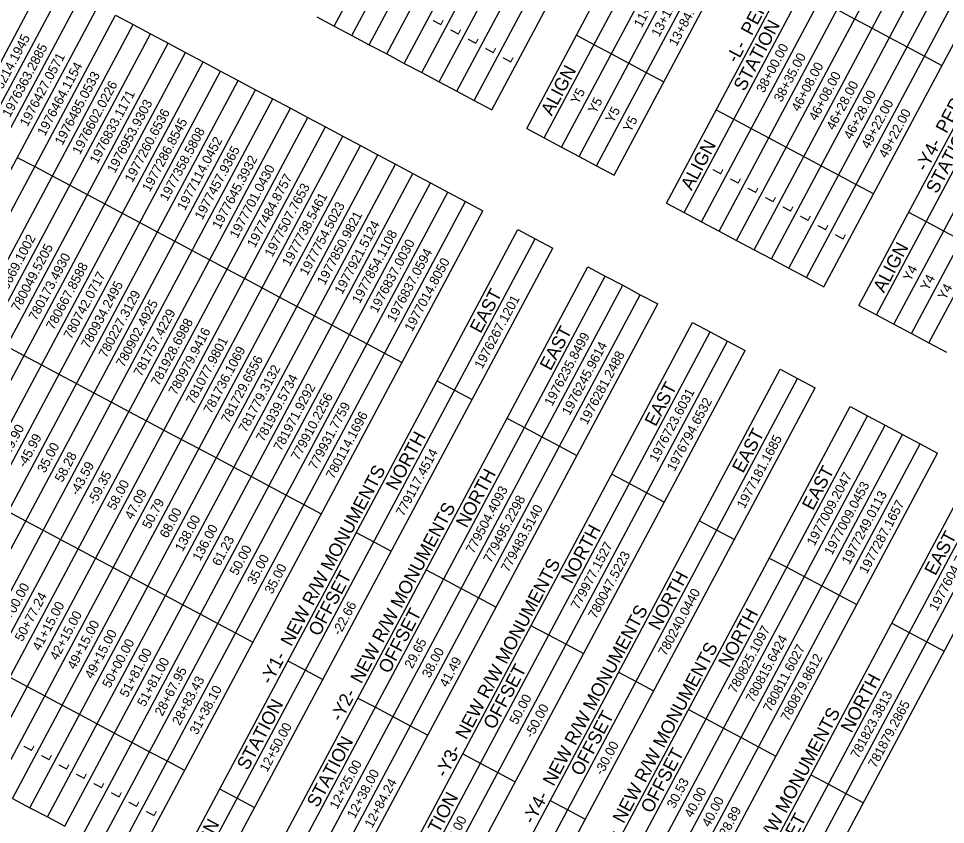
# Model space of a CAD drawing. Extents: x 1979034 to 1987549, y 771535 to 781988.
# Drawn here: x 1981883 to 1984093, y 775446 to 777368 of the extents above; entities that cross this region are included whole.
import ezdxf

# ---------------------------------------------------------------- set-up
doc = ezdxf.new("R2010")
doc.units = 0
for name, color, linetype in [('CTL Sheet Notes CELL', 7, 'Continuous'), ('CTL Sheet Table Cell', 7, 'Continuous'), ('CTL Sheet Text', 7, 'Continuous')]:
    doc.layers.add(name, color=color, linetype=linetype)

msp = doc.modelspace()

# ---------------------------------------------------------------- linework, layer by layer
at = {"layer": 'CTL Sheet Table Cell'}
for p, q in [((1982636.1, 777349.6), (1983465.7, 778906.4)), ((1982677.8, 777327.4), (1983507.4, 778884.1)), ((1982719.5, 777305.2), (1983549.1, 778861.9)), ((1982761.2, 777283), (1983590.8, 778839.7)), ((1982802.9, 777260.7), (1983632.5, 778817.5)), ((1982844.6, 777238.5), (1983674.2, 778795.3)), ((1982886.3, 777216.3), (1983715.9, 778773)), ((1982928, 777194.1), (1983757.6, 778750.8)), ((1982969.7, 777171.8), (1983799.3, 778728.6)), ((1983011.4, 777149.6), (1983841, 778706.4)), ((1983094.8, 777105.2), (1983924.4, 778661.9)), ((1983136.5, 777083), (1983966.1, 778639.7)), ((1983178.2, 777060.7), (1984007.8, 778617.5)), ((1983219.9, 777038.5), (1984049.5, 778595.3)), ((1983261.6, 777016.3), (1984091.2, 778573.1)), ((1983303.3, 776994.1), (1984132.9, 778550.8)), ((1983428.4, 776927.4), (1984258, 778484.2)), ((1983470.1, 776905.2), (1984299.7, 778462)), ((1983511.8, 776883), (1984341.4, 778439.7)), ((1983553.5, 776860.8), (1984383.1, 778417.5)), ((1983595.2, 776838.5), (1984424.8, 778395.3)), ((1983636.9, 776816.3), (1984466.5, 778373.1)), ((1983678.6, 776794.1), (1984508.2, 778350.8)), ((1983720.3, 776771.9), (1984549.9, 778328.6)), ((1983762, 776749.6), (1984591.6, 778306.4)), ((1983803.7, 776727.4), (1984633.3, 778284.2)), ((1983887.1, 776683), (1984716.7, 778239.7)), ((1983928.8, 776660.8), (1984758.4, 778217.5)), ((1983970.5, 776638.5), (1984800.1, 778195.3)), ((1984012.2, 776616.3), (1984841.7, 778173.1)), ((1984053.9, 776594.1), (1984883.4, 778150.9)), ((1981118.2, 775907.8), (1981947.8, 777464.6)), ((1981159.9, 775885.6), (1981989.5, 777442.3)), ((1981201.6, 775863.4), (1982031.2, 777420.1)), ((1981243.3, 775841.1), (1982072.9, 777397.9)), ((1983834.9, 777388.9), (1983876.6, 777366.7)), ((1981285, 775818.9), (1982114.6, 777375.7)), ((1982114.6, 777375.7), (1982156.3, 777353.5)), ((1982594.4, 777371.8), (1982636.1, 777349.6)), ((1983876.6, 777366.7), (1983918.3, 777344.5)), ((1981326.7, 775796.7), (1982156.3, 777353.5)), ((1982156.3, 777353.5), (1982198, 777331.2)), ((1982636.1, 777349.6), (1982677.8, 777327.4)), ((1983918.3, 777344.5), (1983960, 777322.3)), ((1981368.4, 775774.5), (1982198, 777331.2)), ((1982198, 777331.2), (1982239.7, 777309)), ((1982677.8, 777327.4), (1982719.5, 777305.2)), ((1983213.3, 777327.6), (1983255, 777305.4)), ((1983960, 777322.3), (1984001.7, 777300.1)), ((1981410.1, 775752.3), (1982239.7, 777309)), ((1982239.7, 777309), (1982281.4, 777286.8)), ((1982719.5, 777305.2), (1982761.2, 777283)), ((1983255, 777305.4), (1983296.7, 777283.1)), ((1984001.7, 777300.1), (1984043.4, 777277.8)), ((1981451.8, 775730), (1982281.4, 777286.8)), ((1982281.4, 777286.8), (1982323.1, 777264.6)), ((1982761.2, 777283), (1982802.9, 777260.7)), ((1983296.7, 777283.1), (1983338.4, 777260.9)), ((1984043.4, 777277.8), (1984085.1, 777255.6)), ((1981493.5, 775707.8), (1982323.1, 777264.6)), ((1982323.1, 777264.6), (1982364.8, 777242.3)), ((1982802.9, 777260.7), (1982844.6, 777238.5)), ((1983338.4, 777260.9), (1983380.1, 777238.7)), ((1981535.2, 775685.6), (1982364.8, 777242.3)), ((1982364.8, 777242.3), (1982406.5, 777220.1)), ((1982844.6, 777238.5), (1982886.3, 777216.3)), ((1983380.1, 777238.7), (1983421.8, 777216.5)), ((1981576.9, 775663.4), (1982406.5, 777220.1)), ((1982406.5, 777220.1), (1982448.2, 777197.9)), ((1982886.3, 777216.3), (1982928, 777194.1)), ((1981618.6, 775641.1), (1982448.2, 777197.9)), ((1982448.2, 777197.9), (1982489.9, 777175.7)), ((1982928, 777194.1), (1982969.7, 777171.8)), ((1981660.3, 775618.9), (1982489.9, 777175.7)), ((1982489.9, 777175.7), (1982531.6, 777153.5)), ((1982969.7, 777171.8), (1983011.4, 777149.6)), ((1981702, 775596.7), (1982531.6, 777153.5)), ((1982531.6, 777153.5), (1982573.3, 777131.2)), ((1983546.9, 777149.8), (1983588.6, 777127.6)), ((1981743.7, 775574.5), (1982573.3, 777131.2)), ((1982573.3, 777131.2), (1982615, 777109)), ((1983588.6, 777127.6), (1983630.3, 777105.4)), ((1981785.4, 775552.3), (1982615, 777109)), ((1982615, 777109), (1982656.7, 777086.8)), ((1983094.8, 777105.2), (1983136.5, 777083)), ((1983630.3, 777105.4), (1983672, 777083.1)), ((1981827.1, 775530), (1982656.7, 777086.8)), ((1982656.7, 777086.8), (1982698.4, 777064.6)), ((1983136.5, 777083), (1983178.2, 777060.7)), ((1983672, 777083.1), (1983713.7, 777060.9)), ((1981868.8, 775507.8), (1982698.4, 777064.6)), ((1982698.4, 777064.6), (1982740.1, 777042.4)), ((1983178.2, 777060.7), (1983219.9, 777038.5)), ((1983713.7, 777060.9), (1983755.4, 777038.7)), ((1981880.3, 777036.5), (1981922, 777014.3)), ((1981910.5, 775485.6), (1982740.1, 777042.4)), ((1982740.1, 777042.4), (1982781.8, 777020.1)), ((1983219.9, 777038.5), (1983261.6, 777016.3)), ((1983755.4, 777038.7), (1983797.1, 777016.5)), ((1981922, 777014.3), (1981963.7, 776992.1)), ((1981952.2, 775463.4), (1982781.8, 777020.1)), ((1982781.8, 777020.1), (1982823.5, 776997.9)), ((1983261.6, 777016.3), (1983303.3, 776994.1)), ((1983797.1, 777016.5), (1983838.8, 776994.3)), ((1981963.7, 776992.1), (1982005.4, 776969.8)), ((1981993.9, 775441.2), (1982823.5, 776997.9)), ((1982823.5, 776997.9), (1982865.2, 776975.7)), ((1983838.8, 776994.3), (1983880.5, 776972)), ((1982005.4, 776969.8), (1982047.1, 776947.6)), ((1982035.6, 775418.9), (1982865.2, 776975.7)), ((1982865.2, 776975.7), (1982906.9, 776953.5)), ((1983880.5, 776972), (1983922.2, 776949.8)), ((1982047.1, 776947.6), (1982088.8, 776925.4)), ((1982077.3, 775396.7), (1982906.9, 776953.5)), ((1982906.9, 776953.5), (1982948.6, 776931.3)), ((1982088.8, 776925.4), (1982130.5, 776903.2)), ((1982119, 775374.5), (1982948.6, 776931.3)), ((1982948.6, 776931.3), (1982990.3, 776909)), ((1983428.4, 776927.4), (1983470.1, 776905.2)), ((1982130.5, 776903.2), (1982172.2, 776881)), ((1982160.7, 775352.3), (1982990.3, 776909)), ((1983470.1, 776905.2), (1983511.8, 776883)), ((1984005.6, 776905.4), (1984047.3, 776883.2)), ((1982172.2, 776881), (1982213.9, 776858.7)), ((1983511.8, 776883), (1983553.5, 776860.8)), ((1984047.3, 776883.2), (1984089, 776860.9)), ((1982213.9, 776858.7), (1982255.6, 776836.5)), ((1982244.1, 775307.8), (1983073.7, 776864.6)), ((1983073.7, 776864.6), (1983115.4, 776842.4)), ((1983553.5, 776860.8), (1983595.2, 776838.5)), ((1984089, 776860.9), (1984130.7, 776838.7)), ((1982255.6, 776836.5), (1982297.3, 776814.3)), ((1982285.8, 775285.6), (1983115.4, 776842.4)), ((1983115.4, 776842.4), (1983157.1, 776820.1)), ((1983595.2, 776838.5), (1983636.9, 776816.3)), ((1982297.3, 776814.3), (1982339, 776792.1)), ((1982327.5, 775263.4), (1983157.1, 776820.1)), ((1983636.9, 776816.3), (1983678.6, 776794.1)), ((1982339, 776792.1), (1982380.7, 776769.9)), ((1983678.6, 776794.1), (1983720.3, 776771.9)), ((1982380.7, 776769.9), (1982422.4, 776747.6)), ((1982410.9, 775218.9), (1983240.5, 776775.7)), ((1983240.5, 776775.7), (1983282.2, 776753.5)), ((1983720.3, 776771.9), (1983762, 776749.6)), ((1982422.4, 776747.6), (1982464.1, 776725.4)), ((1982452.6, 775196.7), (1983282.2, 776753.5)), ((1983282.2, 776753.5), (1983323.9, 776731.3)), ((1983762, 776749.6), (1983803.7, 776727.4)), ((1982464.1, 776725.4), (1982505.8, 776703.2)), ((1982494.3, 775174.5), (1983323.9, 776731.3)), ((1983323.9, 776731.3), (1983365.5, 776709)), ((1982505.8, 776703.2), (1982547.5, 776681)), ((1982536, 775152.3), (1983365.5, 776709)), ((1983365.5, 776709), (1983407.2, 776686.8)), ((1982547.5, 776681), (1982589.2, 776658.7)), ((1982577.7, 775130.1), (1983407.2, 776686.8)), ((1983887.1, 776683), (1983928.8, 776660.8)), ((1982589.2, 776658.7), (1982630.9, 776636.5)), ((1983928.8, 776660.8), (1983970.5, 776638.5)), ((1982630.9, 776636.5), (1982672.6, 776614.3)), ((1982661.1, 775085.6), (1983490.6, 776642.4)), ((1983490.6, 776642.4), (1983532.3, 776620.2)), ((1983970.5, 776638.5), (1984012.2, 776616.3)), ((1982672.6, 776614.3), (1982714.3, 776592.1)), ((1982702.8, 775063.4), (1983532.3, 776620.2)), ((1983532.3, 776620.2), (1983574, 776597.9)), ((1984012.2, 776616.3), (1984053.9, 776594.1)), ((1981854.5, 776586.2), (1981896.2, 776564)), ((1982714.3, 776592.1), (1982756, 776569.9)), ((1982744.5, 775041.2), (1983574, 776597.9)), ((1983574, 776597.9), (1983615.7, 776575.7)), ((1984053.9, 776594.1), (1984095.6, 776571.9)), ((1981896.2, 776564), (1981937.9, 776541.8)), ((1982756, 776569.9), (1982797.7, 776547.6)), ((1982786.2, 775019), (1983615.7, 776575.7)), ((1981937.9, 776541.8), (1981979.6, 776519.6)), ((1981979.6, 776519.6), (1982021.3, 776497.3)), ((1982869.6, 774974.5), (1983699.1, 776531.3)), ((1983699.1, 776531.3), (1983740.8, 776509.1)), ((1982021.3, 776497.3), (1982063, 776475.1)), ((1982881.1, 776503.2), (1982922.8, 776481)), ((1982911.3, 774952.3), (1983740.8, 776509.1)), ((1983740.8, 776509.1), (1983782.5, 776486.8)), ((1982063, 776475.1), (1982104.7, 776452.9)), ((1982922.8, 776481), (1982964.5, 776458.8)), ((1982953, 774930.1), (1983782.5, 776486.8)), ((1982104.7, 776452.9), (1982146.4, 776430.7)), ((1982146.4, 776430.7), (1982188.1, 776408.5)), ((1983036.3, 774885.6), (1983865.9, 776442.4)), ((1983865.9, 776442.4), (1983907.6, 776420.2)), ((1982188.1, 776408.5), (1982229.8, 776386.2)), ((1983047.9, 776414.3), (1983089.6, 776392.1)), ((1983078, 774863.4), (1983907.6, 776420.2)), ((1983907.6, 776420.2), (1983949.3, 776397.9)), ((1982229.8, 776386.2), (1982271.5, 776364)), ((1983089.6, 776392.1), (1983131.3, 776369.9)), ((1983119.7, 774841.2), (1983949.3, 776397.9)), ((1983949.3, 776397.9), (1983991, 776375.7)), ((1982271.5, 776364), (1982313.2, 776341.8)), ((1983131.3, 776369.9), (1983173, 776347.7)), ((1983161.4, 774819), (1983991, 776375.7)), ((1983991, 776375.7), (1984032.7, 776353.5)), ((1982313.2, 776341.8), (1982354.9, 776319.6)), ((1983173, 776347.7), (1983214.7, 776325.4)), ((1983203.1, 774796.7), (1984032.7, 776353.5)), ((1984032.7, 776353.5), (1984074.4, 776331.3)), ((1982354.9, 776319.6), (1982396.6, 776297.4)), ((1983244.8, 774774.5), (1984074.4, 776331.3)), ((1982396.6, 776297.4), (1982438.3, 776275.1)), ((1982438.3, 776275.1), (1982480, 776252.9)), ((1983298.1, 776281), (1983339.8, 776258.8)), ((1983328.2, 774730.1), (1984157.8, 776286.8)), ((1982480, 776252.9), (1982521.7, 776230.7)), ((1983339.8, 776258.8), (1983381.5, 776236.5)), ((1983369.9, 774707.9), (1984199.5, 776264.6)), ((1982521.7, 776230.7), (1982563.4, 776208.5)), ((1983381.5, 776236.5), (1983423.2, 776214.3)), ((1983411.6, 774685.6), (1984241.2, 776242.4)), ((1982563.4, 776208.5), (1982605.1, 776186.3)), ((1983453.3, 774663.4), (1984282.9, 776220.2)), ((1981858.4, 776191.6), (1981900.1, 776169.3)), ((1981900.1, 776169.3), (1981941.8, 776147.1)), ((1983506.6, 776169.9), (1983548.3, 776147.7)), ((1981941.8, 776147.1), (1981983.5, 776124.9)), ((1982688.5, 776141.8), (1982730.2, 776119.6)), ((1983548.3, 776147.7), (1983590, 776125.4)), ((1981983.5, 776124.9), (1982025.2, 776102.7)), ((1982730.2, 776119.6), (1982771.9, 776097.4)), ((1982025.2, 776102.7), (1982066.9, 776080.4)), ((1982066.9, 776080.4), (1982108.6, 776058.2)), ((1983673.4, 776081), (1983715.1, 776058.8)), ((1982108.6, 776058.2), (1982150.2, 776036)), ((1982855.3, 776052.9), (1982897, 776030.7)), ((1983715.1, 776058.8), (1983756.7, 776036.6)), ((1982150.2, 776036), (1982191.9, 776013.8)), ((1982897, 776030.7), (1982938.7, 776008.5)), ((1983756.7, 776036.6), (1983798.4, 776014.3)), ((1982191.9, 776013.8), (1982233.6, 775991.6)), ((1982938.7, 776008.5), (1982980.4, 775986.3)), ((1983798.4, 776014.3), (1983840.1, 775992.1)), ((1982233.6, 775991.6), (1982275.3, 775969.3)), ((1982980.4, 775986.3), (1983022.1, 775964)), ((1983840.1, 775992.1), (1983881.8, 775969.9)), ((1982275.3, 775969.3), (1982317, 775947.1)), ((1982317, 775947.1), (1982358.7, 775924.9)), ((1982358.7, 775924.9), (1982400.4, 775902.7)), ((1983105.5, 775919.6), (1983147.2, 775897.4)), ((1983965.2, 775925.5), (1984006.9, 775903.2)), ((1982400.4, 775902.7), (1982442.1, 775880.5)), ((1983147.2, 775897.4), (1983188.9, 775875.2)), ((1984006.9, 775903.2), (1984048.6, 775881)), ((1983188.9, 775875.2), (1983230.6, 775852.9)), ((1984048.6, 775881), (1984090.3, 775858.8)), ((1982525.5, 775836), (1982567.2, 775813.8)), ((1982567.2, 775813.8), (1982608.9, 775791.6)), ((1983314, 775808.5), (1983355.7, 775786.3)), ((1981862.2, 775796.9), (1981903.9, 775774.7)), ((1983355.7, 775786.3), (1983397.4, 775764.1)), ((1981903.9, 775774.7), (1981945.6, 775752.4)), ((1981945.6, 775752.4), (1981987.3, 775730.2)), ((1982692.3, 775747.1), (1982734, 775724.9)), ((1981987.3, 775730.2), (1982029, 775708)), ((1982734, 775724.9), (1982775.7, 775702.7)), ((1983480.8, 775719.6), (1983522.5, 775697.4)), ((1982029, 775708), (1982070.7, 775685.8)), ((1982775.7, 775702.7), (1982817.4, 775680.5)), ((1983522.5, 775697.4), (1983564.2, 775675.2)), ((1982070.7, 775685.8), (1982112.4, 775663.6)), ((1982817.4, 775680.5), (1982859.1, 775658.2)), ((1983564.2, 775675.2), (1983605.9, 775652.9)), ((1982112.4, 775663.6), (1982154.1, 775641.3)), ((1983605.9, 775652.9), (1983647.6, 775630.7)), ((1982154.1, 775641.3), (1982195.8, 775619.1)), ((1983647.6, 775630.7), (1983689.3, 775608.5)), ((1982195.8, 775619.1), (1982237.5, 775596.9)), ((1982942.5, 775613.8), (1982984.2, 775591.6)), ((1982237.5, 775596.9), (1982279.2, 775574.7)), ((1982984.2, 775591.6), (1983025.9, 775569.4)), ((1983025.9, 775569.4), (1983067.6, 775547.1)), ((1983772.7, 775564.1), (1983814.4, 775541.8)), ((1983814.4, 775541.8), (1983856.1, 775519.6)), ((1982362.6, 775530.2), (1982404.3, 775508)), ((1983856.1, 775519.6), (1983897.8, 775497.4)), ((1981868.8, 775507.8), (1981910.5, 775485.6)), ((1982404.3, 775508), (1982446, 775485.8)), ((1983151, 775502.7), (1983192.7, 775480.5)), ((1981910.5, 775485.6), (1981952.2, 775463.4)), ((1983192.7, 775480.5), (1983234.4, 775458.3)), ((1981952.2, 775463.4), (1981993.9, 775441.2))]:
    msp.add_line(p, q, dxfattribs=at)

# ---------------------------------------------------------------- texts
at = {"layer": 'CTL Sheet Notes CELL'}
for s, p in [('-L-  PERMANENT DRAINAGE EASEMENTS', (1983596.2, 777259)), ('-Y4-  PERMANENT DRAINAGE EASEMENTS', (1984047.5, 777000.8)), ('STATION', (1983614.1, 777192.3)), ('ALIGN', (1983154.5, 777133.5)), ('STATION', (1984072.8, 776947.8)), ('ALIGN', (1983488.1, 776955.7)), ('ALIGN', (1983946.8, 776711.3)), ('EAST', (1982985.2, 776614.8)), ('EAST', (1983152, 776525.9)), ('EAST', (1983402.2, 776392.6)), ('NORTH', (1982785.2, 776239.6)), ('EAST', (1983610.7, 776281.5)), ('-Y1-  NEW R/W MONUMENTS', (1982485.3, 775777.3)), ('NORTH', (1982952, 776150.7)), ('EAST', (1983777.4, 776192.6)), ('-Y2-  NEW R/W MONUMENTS', (1982652.1, 775688.5)), ('NORTH', (1983202.2, 776017.4)), ('EAST', (1984069.3, 776037.1)), ('-Y3-  NEW R/W MONUMENTS', (1982902.3, 775555.1)), ('OFFSET', (1982600.1, 775892.3)), ('NORTH', (1983410.7, 775906.3)), ('OFFSET', (1982766.9, 775803.4)), ('-Y4-  NEW R/W MONUMENTS', (1983110.8, 775444)), ('NORTH', (1983577.5, 775817.4)), ('-Y5-  NEW R/W MONUMENTS', (1983277.6, 775355.1)), ('OFFSET', (1983017.1, 775670)), ('NORTH', (1983869.4, 775661.9)), ('STATION', (1982429.8, 775572.7)), ('OFFSET', (1983225.6, 775558.9)), ('-Y6-  NEW R/W MONUMENTS', (1983569.5, 775199.6)), ('STATION', (1982596.6, 775483.8)), ('OFFSET', (1983392.4, 775470.1)), ('STATION', (1982846.8, 775350.5)), ('ALIGN', (1982303.8, 775336.2)), ('OFFSET', (1983684.3, 775314.5))]:
    msp.add_text(s, height=31.5, rotation=61.9471, dxfattribs=at).set_placement(p)
at = {"layer": 'CTL Sheet Text'}
for s, p in [('11+88.00', (1983368.7, 777344.1)), ('13+11.00', (1983410.4, 777321.9)), ('13+84.00', (1983452.1, 777299.7)), ('L', (1982889.4, 777349)), ('L', (1982931.1, 777326.7)), ('1976214.1945', (1981821, 777152.5)), ('L', (1982972.8, 777304.5)), ('1976363.2885', (1981862.7, 777130.3)), ('L', (1983014.5, 777282.3)), ('38+00.00', (1983660.6, 777188.6)), ('1976427.0571', (1981904.4, 777108.1)), ('L', (1983056.2, 777260.1)), ('38+35.00', (1983702.3, 777166.3)), ('1976464.1154', (1981946.1, 777085.9)), ('46+08.00', (1983744, 777144.1)), ('1976485.0533', (1981987.8, 777063.7)), ('46+08.00', (1983785.7, 777121.9)), ('1976602.0226', (1982029.5, 777041.4)), ('Y5', (1983217.8, 777161.3)), ('46+28.00', (1983827.4, 777099.7)), ('1976833.1171', (1982071.2, 777019.2)), ('Y5', (1983259.5, 777139.1)), ('46+28.00', (1983869.1, 777077.5)), ('1976953.9303', (1982112.9, 776997)), ('Y5', (1983301.2, 777116.9)), ('49+22.00', (1983910.8, 777055.2)), ('1977260.6536', (1982154.6, 776974.8)), ('Y5', (1983342.9, 777094.7)), ('49+22.00', (1983952.5, 777033)), ('1977286.8545', (1982196.3, 776952.6)), ('1977358.5808', (1982238, 776930.3)), ('1977114.0452', (1982279.7, 776908.1)), ('1977457.9365', (1982321.4, 776885.9)), ('1977645.3932', (1982363.1, 776863.7)), ('1977701.0430', (1982404.8, 776841.4)), ('L', (1983556.6, 776993.4)), ('1977484.8757', (1982446.5, 776819.2)), ('L', (1983598.3, 776971.2)), ('1977507.7653', (1982488.2, 776797)), ('L', (1983640, 776949)), ('1977738.5461', (1982529.9, 776774.8)), ('L', (1983681.7, 776926.8)), ('1977754.5023', (1982571.6, 776752.6)), ('L', (1983723.4, 776904.5)), ('1977850.9821', (1982613.3, 776730.3)), ('L', (1983765.1, 776882.3)), ('1977921.5124', (1982655, 776708.1)), ('L', (1983806.8, 776860.1)), ('779669.1002', (1981842.2, 776689.9)), ('1977854.1108', (1982696.7, 776685.9)), ('L', (1983848.5, 776837.9)), ('780049.5205', (1981883.9, 776667.7)), ('1976837.0030', (1982738.4, 776663.7)), ('780173.4930', (1981925.6, 776645.5)), ('1976837.0594', (1982780.1, 776641.5)), ('780667.8588', (1981967.3, 776623.2)), ('1977014.8050', (1982821.8, 776619.2)), ('780742.0717', (1982009, 776601)), ('Y4', (1984010.1, 776739.1)), ('780934.2495', (1982050.7, 776578.8)), ('Y4', (1984051.8, 776716.9)), ('780227.3129', (1982092.4, 776556.6)), ('Y4', (1984093.4, 776694.7)), ('780902.4925', (1982134.1, 776534.4)), ('1976267.1201', (1982988.6, 776530.4)), ('781757.4229', (1982175.8, 776512.1)), ('781928.6988', (1982217.5, 776489.9)), ('780979.9416', (1982259.2, 776467.7)), ('781077.9801', (1982300.9, 776445.5)), ('1976235.8499', (1983155.4, 776441.5)), ('781736.1069', (1982342.6, 776423.2)), ('1976245.9614', (1983197.1, 776419.2)), ('781729.6556', (1982384.3, 776401)), ('1976281.2488', (1983238.8, 776397)), ('781779.3132', (1982426, 776378.8)), ('781939.5734', (1982467.7, 776356.6)), ('781971.9292', (1982509.4, 776334.4)), ('779910.2256', (1982551.1, 776312.1)), ('1976723.6031', (1983405.6, 776308.1)), ('779931.7759', (1982592.8, 776289.9)), ('1976794.6532', (1983447.3, 776285.9)), ('780114.1696', (1982634.5, 776267.7)), ('-49.90', (1981857.5, 776316.7)), ('-45.99', (1981899.2, 776294.5)), ('1977181.1685', (1983614.1, 776197)), ('35.00', (1981946.1, 776282.1)), ('779117.4514', (1982801.3, 776178.8)), ('58.28', (1981987.8, 776259.9)), ('-43.59', (1982024.3, 776227.8)), ('-59.35', (1982066, 776205.6)), ('1977009.2047', (1983780.9, 776108.2)), ('58.00', (1982112.9, 776193.2)), ('779504.4093', (1982968.1, 776089.9)), ('1977009.0453', (1983822.6, 776085.9)), ('47.09', (1982154.6, 776171)), ('779495.2298', (1983009.8, 776067.7)), ('1977249.0113', (1983864.3, 776063.7)), ('50.79', (1982196.3, 776148.8)), ('779483.5140', (1983051.5, 776045.5)), ('1977287.1657', (1983906, 776041.5)), ('68.00', (1982238, 776126.5)), ('138.00', (1982274.5, 776094.5)), ('136.00', (1982316.2, 776072.2)), ('61.23', (1982363.1, 776059.9)), ('779977.1527', (1983218.3, 775956.6)), ('1977604.7042', (1984072.8, 775952.6)), ('50.00', (1982404.8, 776037.6)), ('780047.5223', (1983260, 775934.4)), ('35.00', (1982446.5, 776015.4)), ('35.00', (1982488.2, 775993.2)), ('49+00.00', (1981850.8, 775902.3)), ('780240.0440', (1983426.8, 775845.5)), ('50+77.24', (1981892.5, 775880.1)), ('41+15.00', (1981934.2, 775857.9)), ('-22.66', (1982649.7, 775894.5)), ('42+15.00', (1981975.9, 775835.6)), ('49+15.00', (1982017.6, 775813.4)), ('780825.1097', (1983593.5, 775756.6)), ('49+15.00', (1982059.3, 775791.2)), ('780815.6424', (1983635.2, 775734.4)), ('50+00.00', (1982101, 775769)), ('29.65', (1982821.8, 775815.4)), ('780811.6027', (1983676.9, 775712.2)), ('51+81.00', (1982142.7, 775746.8)), ('38.00', (1982863.5, 775793.2)), ('780879.8612', (1983718.6, 775690)), ('51+81.00', (1982184.4, 775724.5)), ('41.49', (1982905.2, 775771)), ('28+67.95', (1982226.1, 775702.3)), ('28+83.43', (1982267.8, 775680.1)), ('31+38.10', (1982309.5, 775657.9)), ('781823.3813', (1983885.4, 775601.1)), ('50.00', (1983072, 775682.1)), ('781879.2865', (1983927.1, 775578.8)), ('-50.00', (1983108.4, 775650)), ('12+50.00', (1982476.3, 775569)), ('L', (1981913.6, 775618.3)), ('-30.00', (1983275.2, 775561.2)), ('L', (1981955.3, 775596.1)), ('L', (1981997, 775573.8)), ('12+25.00', (1982643.1, 775480.1)), ('L', (1982038.7, 775551.6)), ('12+38.00', (1982684.8, 775457.9)), ('L', (1982080.4, 775529.4)), ('12+84.24', (1982726.5, 775435.7)), ('30.53', (1983447.3, 775482.1)), ('L', (1982122.1, 775507.2)), ('40.00', (1983489, 775459.9)), ('L', (1982163.8, 775484.9)), ('40.00', (1983530.7, 775437.7)), ('L', (1982205.5, 775462.7)), ('-28.89', (1983567.1, 775405.6)), ('12+66.00', (1982893.3, 775346.8))]:
    msp.add_text(s, height=22.5, rotation=61.9471, dxfattribs=at).set_placement(p)

doc.saveas('drawing.dxf')
